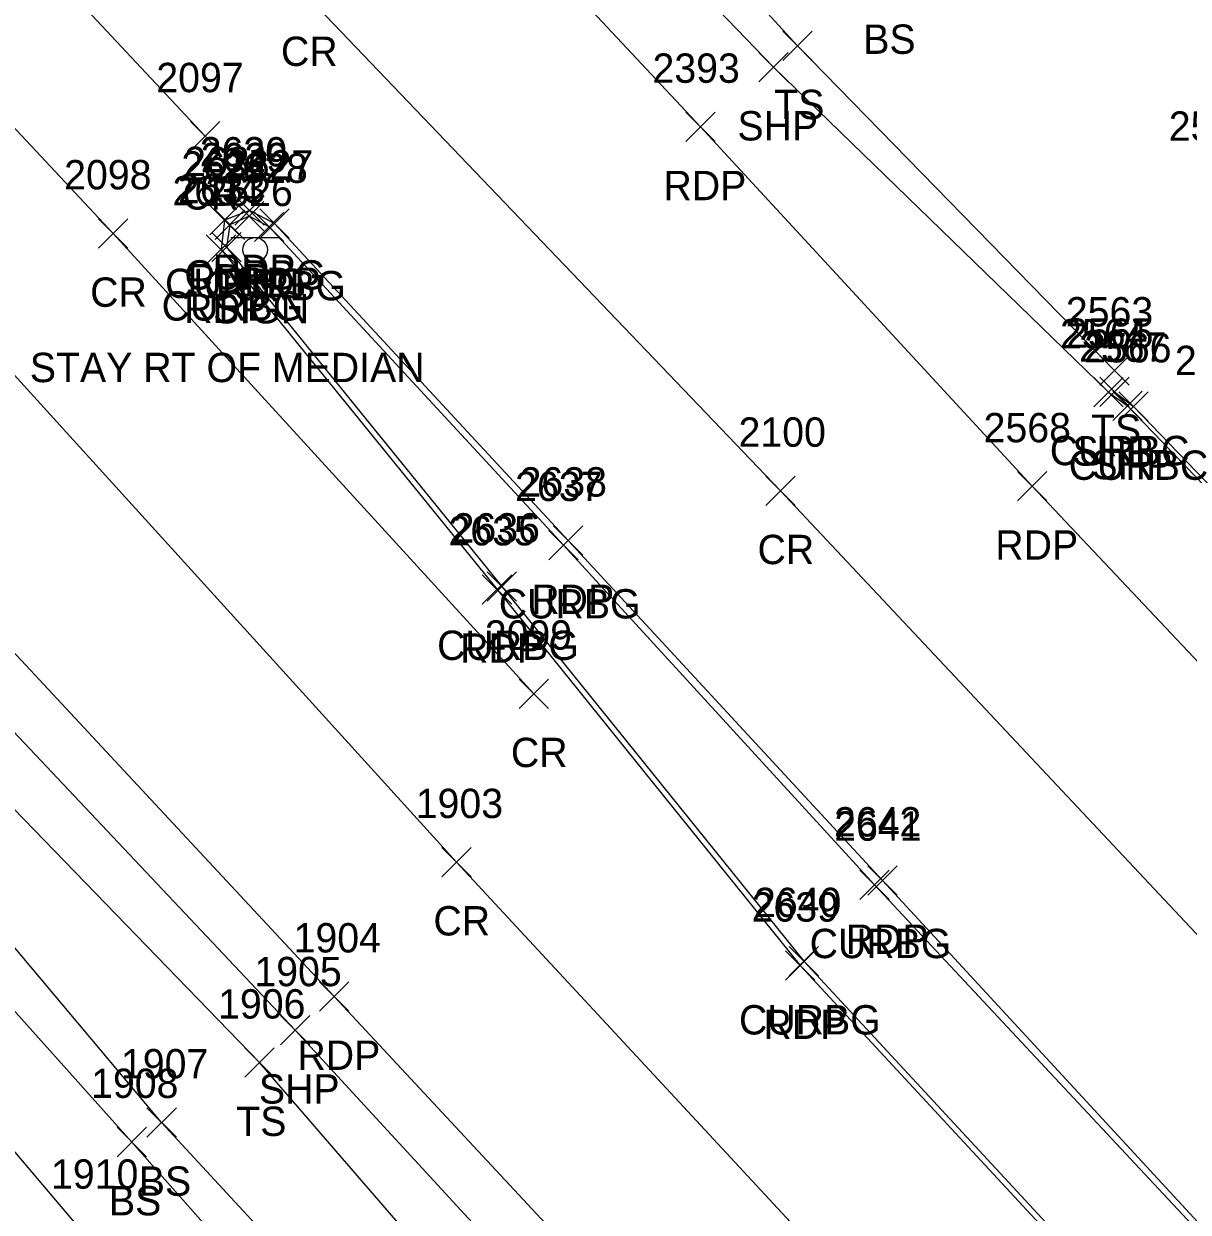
# Model space of a CAD drawing. Extents: x 1623612 to 1625808, y 621345 to 627748.
# Drawn here: x 1624481.9 to 1624561.2, y 626535.9 to 626616.9 of the extents above; entities that cross this region are included whole.
import ezdxf

# ---------------------------------------------------------------- set-up
doc = ezdxf.new("R2010")
doc.units = 0
for name, color, linetype in [('L_A', 7, 'Continuous'), ('L_I', 7, 'Continuous'), ('L_TIC', 7, 'Continuous'), ('LELB', 7, 'Continuous'), ('P_A', 7, 'Continuous'), ('P_I', 7, 'Continuous'), ('P_TIC', 7, 'Continuous'), ('PET', 7, 'Continuous'), ('PRC', 7, 'Continuous'), ('PSP', 7, 'Continuous'), ('R_A', 7, 'Continuous'), ('R_I', 7, 'Continuous'), ('R_TIC', 7, 'Continuous'), ('RC', 7, 'Continuous'), ('S_A', 7, 'Continuous'), ('S_C', 7, 'Continuous'), ('S_I', 7, 'Continuous'), ('SSGN', 7, 'Continuous')]:
    doc.layers.add(name, color=color, linetype=linetype)

msp = doc.modelspace()

# ---------------------------------------------------------------- linework, layer by layer
at = {"layer": 'L_TIC'}
for points in [[(1624533.619, 626614.384), (1624535.619, 626616.384)], [(1624535.619, 626614.384), (1624533.619, 626616.384)], [(1624555.203, 626592.257), (1624557.203, 626594.257)], [(1624557.203, 626592.257), (1624555.203, 626594.257)], [(1624496.966, 626545.096), (1624498.966, 626547.096)], [(1624498.966, 626545.096), (1624496.966, 626547.096)], [(1624490.294, 626541.018), (1624492.294, 626543.018)], [(1624492.294, 626541.018), (1624490.294, 626543.018)], [(1624488.261, 626539.683), (1624490.261, 626541.683)], [(1624490.261, 626539.683), (1624488.261, 626541.683)]]:
    msp.add_lwpolyline(points, dxfattribs=at)
at = {"layer": 'LELB'}
for points in [[(1624396.454, 626785.004), (1624390.024, 626786.006), (1624384.799, 626779.625), (1624385.296, 626768.835), (1624398.497, 626753.75), (1624422.945, 626728.075), (1624450.613, 626700.434), (1624478.976, 626673.904), (1624494.164, 626658.759), (1624513.926, 626637.932), (1624534.619, 626615.384), (1624556.203, 626593.257)], [(1624559.521, 626449.493), (1624534.102, 626480.348), (1624517.665, 626499.951), (1624485.969, 626534.501), (1624453.515, 626572.787), (1624418.498, 626605.529), (1624422.916, 626612.303), (1624431.151, 626614.911), (1624438.463, 626609.804)], [(1624597.716, 626417.916), (1624590.154, 626428.273), (1624581.6, 626439.285), (1624575.062, 626444.113), (1624569.24, 626450.894), (1624572.534, 626454.001), (1624541.737, 626486.68), (1624523.259, 626507.42), (1624491.294, 626542.018), (1624460.521, 626578.646), (1624432.879, 626609.227), (1624426.505, 626611.958), (1624422.61, 626606.726)], [(1624669.801, 626328.277), (1624669.978, 626343.79), (1624664.437, 626357.312), (1624659.039, 626367.017), (1624647.793, 626381.907), (1624630.66, 626395.22), (1624597.454, 626435.364), (1624575.796, 626460.211), (1624547.364, 626492.231), (1624525.956, 626513.705), (1624497.966, 626546.096), (1624463.718, 626581.437), (1624438.463, 626609.804)], [(1624596.27, 626415.378), (1624586.557, 626426.425), (1624565.056, 626445.803), (1624539.411, 626483.846), (1624522.251, 626503.352), (1624489.261, 626540.683), (1624457.415, 626576.251), (1624422.61, 626606.726)]]:
    msp.add_lwpolyline(points, dxfattribs=at)
at = {"layer": 'P_TIC'}
for points in [[(1624531.986, 626612.931), (1624533.986, 626614.931)], [(1624533.986, 626612.931), (1624531.986, 626614.931)], [(1624526.994, 626608.86), (1624528.994, 626610.86)], [(1624528.994, 626608.86), (1624526.994, 626610.86)], [(1624493.268, 626608.221), (1624495.268, 626610.221)], [(1624495.268, 626608.221), (1624493.268, 626610.221)], [(1624496.28, 626603.159), (1624498.28, 626605.159)], [(1624498.28, 626603.159), (1624496.28, 626605.159)], [(1624494.566, 626602.502), (1624496.566, 626604.502)], [(1624496.566, 626602.502), (1624494.566, 626604.502)], [(1624497.981, 626602.269), (1624499.981, 626604.269)], [(1624499.981, 626602.269), (1624497.981, 626604.269)], [(1624497.981, 626602.269), (1624499.981, 626604.269)], [(1624499.981, 626602.269), (1624497.981, 626604.269)], [(1624486.989, 626601.597), (1624488.989, 626603.597)], [(1624488.989, 626601.597), (1624486.989, 626603.597)], [(1624494.337, 626600.502), (1624496.337, 626602.502)], [(1624496.337, 626600.502), (1624494.337, 626602.502)], [(1624554.807, 626590.769), (1624556.807, 626592.769)], [(1624556.807, 626590.769), (1624554.807, 626592.769)], [(1624556.104, 626589.849), (1624558.104, 626591.849)], [(1624558.104, 626589.849), (1624556.104, 626591.849)], [(1624532.456, 626584.06), (1624534.456, 626586.06)], [(1624534.456, 626584.06), (1624532.456, 626586.06)], [(1624549.6, 626584.364), (1624551.6, 626586.364)], [(1624551.6, 626584.364), (1624549.6, 626586.364)], [(1624517.988, 626580.664), (1624519.988, 626582.664)], [(1624519.988, 626580.664), (1624517.988, 626582.664)], [(1624513.141, 626577.336), (1624515.141, 626579.336)], [(1624515.141, 626577.336), (1624513.141, 626579.336)], [(1624515.653, 626570.23), (1624517.653, 626572.23)], [(1624517.653, 626570.23), (1624515.653, 626572.23)], [(1624510.375, 626558.757), (1624512.375, 626560.757)], [(1624512.375, 626558.757), (1624510.375, 626560.757)], [(1624539.403, 626557.501), (1624541.403, 626559.501)], [(1624541.403, 626557.501), (1624539.403, 626559.501)], [(1624533.8, 626551.701), (1624535.8, 626553.701)], [(1624535.8, 626551.701), (1624533.8, 626553.701)], [(1624502.055, 626549.599), (1624504.055, 626551.599)], [(1624504.055, 626549.599), (1624502.055, 626551.599)], [(1624499.384, 626547.299), (1624501.384, 626549.299)], [(1624501.384, 626547.299), (1624499.384, 626549.299)]]:
    msp.add_lwpolyline(points, dxfattribs=at)
at = {"layer": 'PET'}
for points in [[(1624211.356, 626948.939), (1624238.716, 626919.545), (1624262.362, 626893.707), (1624286.047, 626868.279), (1624309.881, 626842.734), (1624340.204, 626808.471), (1624365.336, 626781.16), (1624395.182, 626750.466), (1624419.588, 626724.643), (1624445.912, 626697.016), (1624473.102, 626668.142), (1624507.258, 626632.061), (1624527.994, 626609.86), (1624550.6, 626585.364), (1624578.26, 626556.054), (1624603.3, 626530.62), (1624620.594, 626513.388), (1624649.072, 626495.66), (1624671.176, 626489.458), (1624702.738, 626490.16)], [(1624682.54, 626327.48), (1624678.381, 626346.433), (1624673.338, 626359.162), (1624665.224, 626373.754), (1624654.285, 626387.736), (1624639.331, 626403.949), (1624606.519, 626439.119), (1624581.336, 626466.221), (1624553.071, 626496.912), (1624531.244, 626520.294), (1624503.055, 626550.599), (1624469.832, 626586.281), (1624436.593, 626622.29), (1624410.082, 626650.632), (1624383.72, 626678.98), (1624351.705, 626713.554), (1624321.287, 626745.92), (1624294.741, 626773.91), (1624265.91, 626805.598)], [(1624498.981, 626603.269), (1624497.28, 626604.159), (1624495.566, 626603.502), (1624495.337, 626601.502), (1624514.141, 626578.336), (1624534.8, 626552.701), (1624570.857, 626513.779), (1624602.546, 626479.636), (1624634.48, 626444.982), (1624661.8, 626415.481), (1624685.008, 626390.69)], [(1624498.981, 626603.269), (1624518.988, 626581.664), (1624540.403, 626558.501), (1624576.577, 626519.308), (1624608.93, 626484.397), (1624640.397, 626450.573), (1624660.558, 626428.568), (1624687.755, 626392.945), (1624687.557, 626391.423), (1624686.609, 626390.546), (1624685.008, 626390.69)]]:
    msp.add_lwpolyline(points, dxfattribs=at)
at = {"layer": 'PRC'}
for points in [[(1624202.382, 626941.004), (1624231.947, 626909.328), (1624268.303, 626868.906), (1624305.535, 626828.987), (1624337.859, 626793.812), (1624369.185, 626760.841), (1624403.286, 626724.165), (1624436.757, 626689.12), (1624471.077, 626653.027), (1624500.988, 626619.006), (1624533.456, 626585.06), (1624572.176, 626543.817), (1624598.348, 626515.597), (1624627.035, 626484.265), (1624657.967, 626450.746), (1624685.099, 626421.269), (1624710.887, 626393.932)], [(1624192.118, 626932.455), (1624222.522, 626900.06), (1624257.955, 626861.76), (1624296.144, 626820.931), (1624328.327, 626786.434), (1624360.023, 626752.63), (1624393.531, 626716.711), (1624427.431, 626680.74), (1624459.983, 626645.807), (1624494.268, 626609.221)], [(1624186.127, 626926.237), (1624216.09, 626894.039), (1624252.236, 626855.543), (1624289.907, 626814.883), (1624322.005, 626780.726), (1624353.658, 626746.64), (1624386.671, 626711.082), (1624421.335, 626674.267), (1624454.067, 626638.874), (1624487.989, 626602.597), (1624516.653, 626571.23)], [(1624691.434, 626366.483), (1624669.775, 626388.582), (1624647.938, 626412.244), (1624616.118, 626446.54), (1624589.588, 626475.599), (1624562.812, 626504.239), (1624540.565, 626528.295), (1624511.375, 626559.757), (1624478.759, 626595.668), (1624444.937, 626631.157), (1624418.889, 626658.653), (1624393.007, 626686.501), (1624360.168, 626722.632), (1624331.528, 626753.243), (1624304.466, 626782.709), (1624275.063, 626813.899), (1624246.398, 626843.612), (1624219.02, 626871.903), (1624198.621, 626894.748), (1624176.279, 626917.845)]]:
    msp.add_lwpolyline(points, dxfattribs=at)
at = {"layer": 'PSP'}
for points in [[(1624213.534, 626951.11), (1624241.132, 626921.365), (1624264.766, 626895.798), (1624288.106, 626870.324), (1624312.073, 626845.038), (1624343.912, 626810.119), (1624367.266, 626782.465), (1624384.8, 626765.813), (1624396.961, 626752.526), (1624422.27, 626726.831), (1624449.324, 626699.427), (1624476.731, 626671.473), (1624511.715, 626635.983), (1624532.986, 626613.931), (1624555.807, 626591.769), (1624557.104, 626590.849), (1624584.714, 626562.126), (1624609.167, 626536.977), (1624624.054, 626517.588), (1624651.189, 626501.536), (1624672.807, 626495.101), (1624698.383, 626495.378)], [(1624676.549, 626327.478), (1624673.724, 626344.862), (1624670.578, 626356.081), (1624664.109, 626370.706), (1624652.391, 626385.591), (1624636.517, 626401.605), (1624603.462, 626436.72), (1624579, 626463.665), (1624550.01, 626494.209), (1624528.45, 626517.805), (1624500.384, 626548.299), (1624466.854, 626583.846), (1624433.641, 626619.401), (1624408.064, 626646.475), (1624380.641, 626676.315), (1624349.244, 626711.115), (1624317.966, 626743.625), (1624292.138, 626770.883), (1624262.105, 626803.32)]]:
    msp.add_lwpolyline(points, dxfattribs=at)
at = {"layer": 'R_TIC'}
for points in [[(1624496.263, 626602.769), (1624498.263, 626604.769)], [(1624498.263, 626602.769), (1624496.263, 626604.769)], [(1624494.939, 626602.193), (1624496.939, 626604.193)], [(1624496.939, 626602.193), (1624494.939, 626604.193)], [(1624497.613, 626602.039), (1624499.613, 626604.039)], [(1624499.613, 626602.039), (1624497.613, 626604.039)], [(1624497.613, 626602.039), (1624499.613, 626604.039)], [(1624499.613, 626602.039), (1624497.613, 626604.039)], [(1624494.711, 626600.655), (1624496.711, 626602.655)], [(1624496.711, 626600.655), (1624494.711, 626602.655)], [(1624555.218, 626590.802), (1624557.218, 626592.802)], [(1624557.218, 626590.802), (1624555.218, 626592.802)], [(1624556.507, 626589.805), (1624558.507, 626591.805)], [(1624558.507, 626589.805), (1624556.507, 626591.805)], [(1624517.68, 626580.358), (1624519.68, 626582.358)], [(1624519.68, 626580.358), (1624517.68, 626582.358)], [(1624513.477, 626577.531), (1624515.477, 626579.531)], [(1624515.477, 626577.531), (1624513.477, 626579.531)], [(1624538.858, 626557.211), (1624540.858, 626559.211)], [(1624540.858, 626557.211), (1624538.858, 626559.211)], [(1624534.044, 626552.01), (1624536.044, 626554.01)], [(1624536.044, 626552.01), (1624534.044, 626554.01)]]:
    msp.add_lwpolyline(points, dxfattribs=at)
at = {"layer": 'RC'}
for points in [[(1624556.218, 626591.802), (1624557.507, 626590.805), (1624585.012, 626562.265), (1624585.702, 626562.257), (1624586.313, 626562.811), (1624590.623, 626575.246), (1624594.107, 626582.767), (1624601.072, 626592.283), (1624605.899, 626598.141), (1624617.105, 626609.195), (1624640.976, 626631.67)], [(1624498.613, 626603.039), (1624497.263, 626603.769), (1624495.939, 626603.193), (1624495.711, 626601.655), (1624514.477, 626578.531), (1624535.044, 626553.01), (1624571.18, 626513.973), (1624602.7, 626479.932), (1624634.581, 626445.549), (1624662.133, 626415.955), (1624685.302, 626391.005)], [(1624498.613, 626603.039), (1624518.68, 626581.358), (1624539.858, 626558.211), (1624576.353, 626519.139), (1624608.614, 626484.224), (1624640.014, 626450.342), (1624660.245, 626428.365), (1624687.441, 626392.737), (1624687.436, 626391.568), (1624686.424, 626390.887), (1624685.302, 626391.005)]]:
    msp.add_lwpolyline(points, dxfattribs=at)
at = {"layer": 'SSGN'}
for p, q in [((1624496.015, 626602.317), (1624499.349, 626602.317)), ((1624497.662, 626601.483), (1624497.662, 626601.483))]:
    msp.add_line(p, q, dxfattribs=at)
msp.add_circle((1624497.662, 626601.483), 0.833, dxfattribs=at)

# ---------------------------------------------------------------- texts
at = {"layer": 'L_A'}
for s, p in [('BS', (1624539.094, 626614.833)), ('TS', (1624533.029, 626610.384)), ('TS', (1624554.612, 626588.257)), ('TS', (1624496.375, 626541.096)), ('BS', (1624489.735, 626537.018)), ('BS', (1624487.702, 626535.683))]:
    msp.add_text(s, height=2, dxfattribs=at).set_placement(p)
at = {"layer": 'L_I'}
for s, p in [('2523', (1624559.908, 626608.912)), ('2563', (1624552.896, 626596.257)), ('1906', (1624495.139, 626549.096)), ('1907', (1624488.522, 626545.018)), ('1908', (1624486.489, 626543.683)), ('1910', (1624483.757, 626537.501))]:
    msp.add_text(s, height=2, dxfattribs=at).set_placement(p)
at = {"layer": 'P_A'}
for s, p in [('CR', (1624499.422, 626614.006)), ('SHP', (1624530.522, 626608.931)), ('CR', (1624492.701, 626604.221)), ('RDP', (1624525.482, 626604.86)), ('RDP', (1624494.769, 626599.159)), ('RDP', (1624493.054, 626598.502)), ('RDP', (1624496.469, 626598.269)), ('RDP', (1624496.469, 626598.269)), ('CR', (1624486.422, 626597.597)), ('RDP', (1624492.825, 626596.502)), ('SHP', (1624553.343, 626586.769)), ('SHP', (1624554.64, 626585.849)), ('CR', (1624531.889, 626580.06)), ('RDP', (1624548.088, 626580.364)), ('RDP', (1624516.477, 626576.664)), ('RDP', (1624511.63, 626573.336)), ('CR', (1624515.086, 626566.23)), ('CR', (1624509.808, 626554.757)), ('RDP', (1624537.892, 626553.501)), ('RDP', (1624532.289, 626547.701)), ('RDP', (1624500.543, 626545.599)), ('SHP', (1624497.919, 626543.299))]:
    msp.add_text(s, height=2, dxfattribs=at).set_placement(p)
at = {"layer": 'P_I'}
for s, p in [('2393', (1624524.734, 626612.86)), ('2097', (1624490.93, 626612.221)), ('2630', (1624493.887, 626607.159)), ('2631', (1624492.826, 626606.502)), ('2627', (1624495.674, 626606.269)), ('2627', (1624495.674, 626606.269)), ('2098', (1624484.65, 626605.597)), ('2634', (1624492.03, 626604.502)), ('2564', (1624552.5, 626594.769)), ('2567', (1624553.797, 626593.849)), ('2100', (1624530.597, 626588.06)), ('2568', (1624547.293, 626588.364)), ('2638', (1624515.681, 626584.664)), ('2635', (1624510.834, 626581.336)), ('2099', (1624513.307, 626574.23)), ('1903', (1624508.603, 626562.757)), ('2642', (1624537.096, 626561.501)), ('2639', (1624531.485, 626555.701)), ('1904', (1624500.283, 626553.599)), ('1905', (1624497.612, 626551.299))]:
    msp.add_text(s, height=2, dxfattribs=at).set_placement(p)
at = {"layer": 'R_A'}
for s, p in [('CURBG', (1624492.846, 626598.769)), ('CURBG', (1624491.522, 626598.193)), ('CURBG', (1624494.196, 626598.039)), ('CURBG', (1624494.196, 626598.039)), ('CURBG', (1624491.293, 626596.655)), ('CURBC', (1624551.801, 626586.802)), ('CURBC', (1624553.09, 626585.805)), ('CURBG', (1624514.262, 626576.358)), ('CURBG', (1624510.06, 626573.531)), ('CURBG', (1624535.441, 626553.211)), ('CURBG', (1624530.626, 626548.01))]:
    msp.add_text(s, height=2, dxfattribs=at).set_placement(p)
at = {"layer": 'R_I'}
for s, p in [('2629', (1624493.948, 626606.769)), ('2632', (1624492.632, 626606.193)), ('2628', (1624495.306, 626606.039)), ('2628', (1624495.306, 626606.039)), ('2633', (1624492.403, 626604.655)), ('2565', (1624552.911, 626594.802)), ('2566', (1624554.145, 626593.805)), ('2562', (1624560.328, 626592.943)), ('2637', (1624515.373, 626584.358)), ('2636', (1624511.115, 626581.531)), ('2641', (1624537.118, 626561.211)), ('2640', (1624531.65, 626556.01))]:
    msp.add_text(s, height=2, dxfattribs=at).set_placement(p)
at = {"layer": 'S_A'}
msp.add_text('SIGN', height=2, dxfattribs=at).set_placement((1624494.8, 626596.463))
at = {"layer": 'S_C'}
msp.add_text('STAY RT OF MEDIAN', height=2, dxfattribs=at).set_placement((1624482.312, 626592.463))
at = {"layer": 'S_I'}
msp.add_text('2626', height=2, dxfattribs=at).set_placement((1624494.28, 626604.463))

doc.saveas('drawing.dxf')
